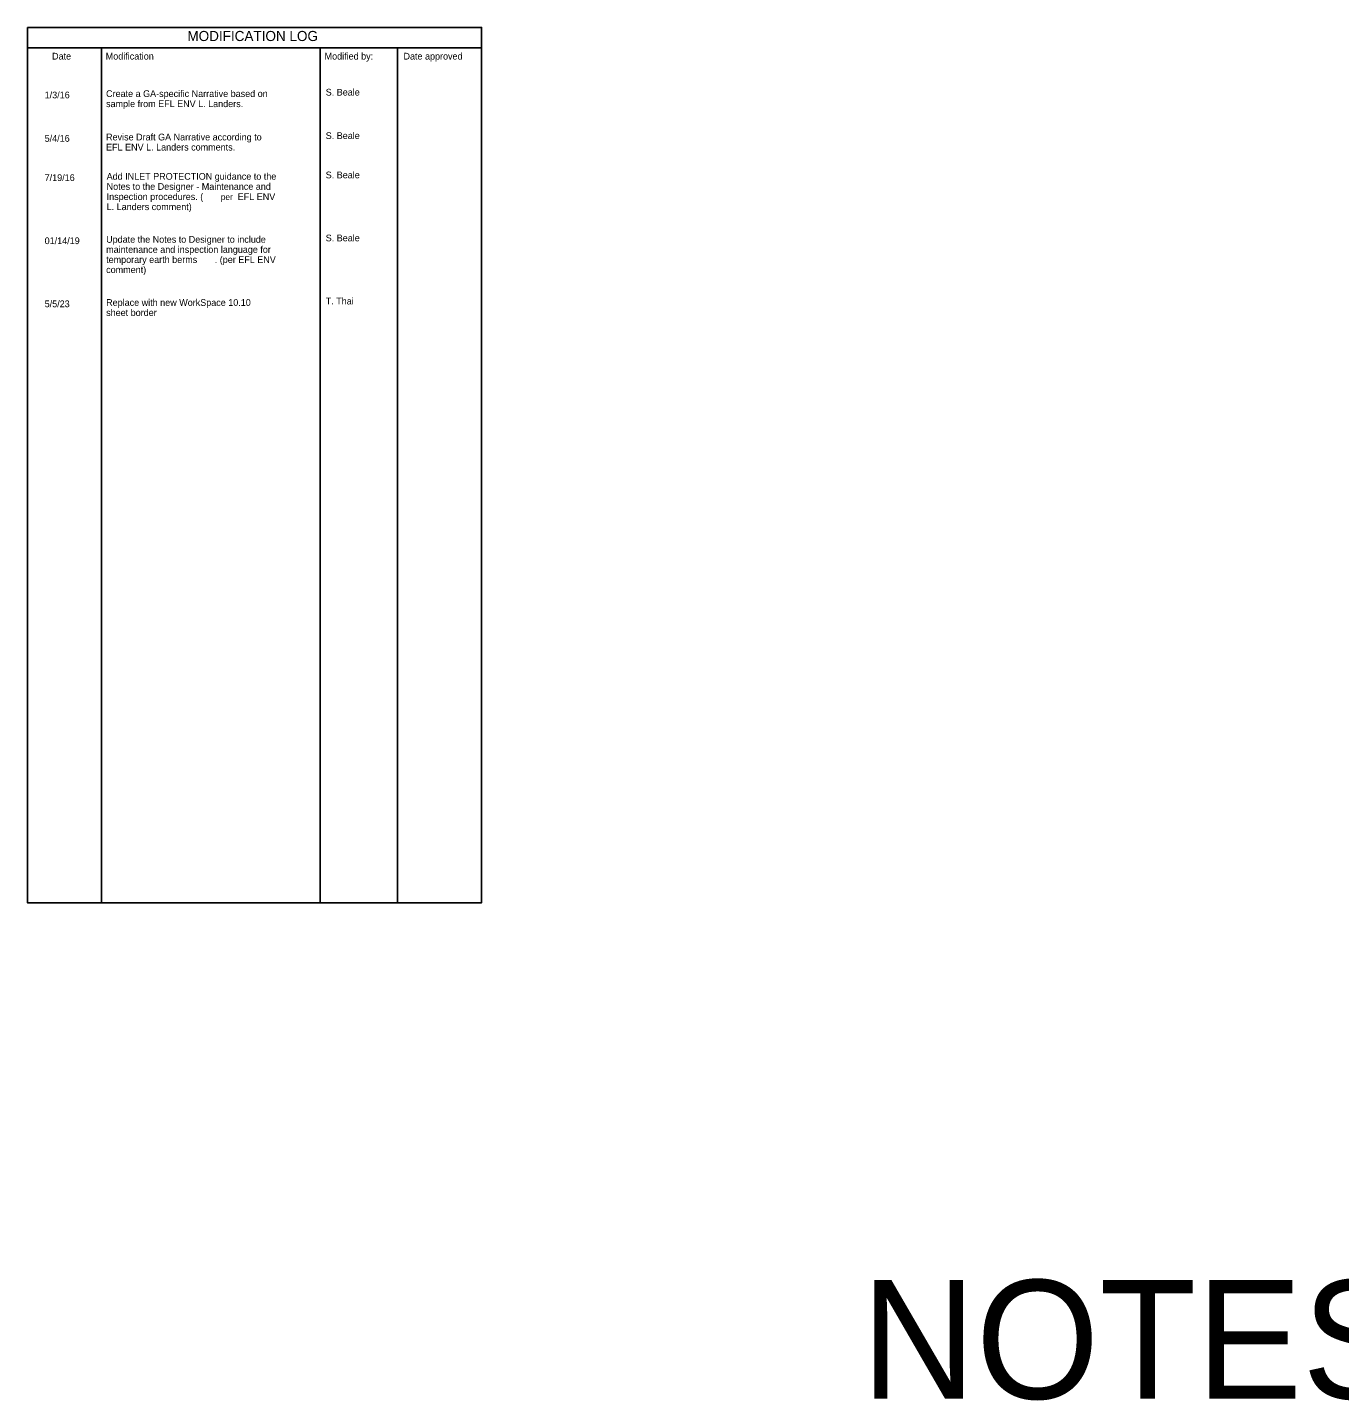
# Model space of a CAD drawing. Extents: x -126 to 11774, y -1769 to 1078.
# Drawn here: x -19 to 1540, y -1769 to -137 of the extents above; entities that cross this region are included whole.
import ezdxf

# ---------------------------------------------------------------- set-up
doc = ezdxf.new("R2010")
doc.units = 0
doc.layers.add('D_Tables', color=7, linetype='Continuous')
doc.layers.add('Default', color=7, linetype='Continuous')

msp = doc.modelspace()

# ---------------------------------------------------------------- linework, layer by layer
at = {"layer": 'D_Tables'}
for p, q in [((-19.4, -161.2), (520.6, -161.2)), ((68.6, -161.2), (68.6, -1177.2)), ((328.6, -161.2), (328.6, -1177.2)), ((420.6, -161.2), (420.6, -1177.2))]:
    msp.add_line(p, q, dxfattribs=at)
msp.add_lwpolyline([(-19.4, -137.2), (520.6, -137.2), (520.6, -1177.2), (-19.4, -1177.2)], close=True, dxfattribs=at)

# ---------------------------------------------------------------- texts
for s, height, p in [('MODIFICATION LOG', 12.008, (170.8, -153.3)), ('Date', 8.01, (9.9, -175.3)), ('Modification', 8.005, (73.7, -175.3)), ('Modified by:', 8.005, (333.9, -175.3)), ('Date approved', 8.005, (427.7, -175.3)), ('S. Beale', 8.01, (335.2, -218.1)), ('S. Beale', 8.01, (335.2, -269.7)), ('Add INLET PROTECTION guidance to the', 8.005, (74.8, -318.1)), ('S. Beale', 8.01, (335.2, -316.4)), ('Notes to the Designer - Maintenance and', 8.005, (74.8, -330.1)), ('Inspection procedures. (', 8.005, (74.8, -342.2)), ('per ', 7.34, (210.5, -342.2)), ('EFL ENV ', 8.01, (230.6, -342.2)), ('L. Landers comment)', 8.005, (74.8, -354.2))]:
    msp.add_text(s, height=height, rotation=360, dxfattribs=at).set_placement(p)
for s, height, p in [('Create a GA-specific Narrative based on', 8.005, (74.1, -219.8)), ('1/3/16', 8.01, (1.1, -221.4)), ('sample from EFL ENV L. Landers.', 8.005, (74.1, -231.8)), ('5/4/16', 8.01, (1.1, -273)), ('Revise Draft GA Narrative according to', 8.005, (74.1, -271.4)), ('EFL ENV L. Landers comments.', 8.005, (74.1, -283.4)), ('7/19/16', 8.01, (1.1, -319.6)), ('01/14/19', 8.01, (1.1, -394.6)), ('Update the Notes to Designer to include', 8.005, (74.2, -393)), ('S. Beale', 8.01, (335.2, -391.3)), ('maintenance and inspection language for', 8.005, (74.2, -405)), ('temporary earth berms', 8.005, (74.2, -417)), ('comment)', 8.01, (74.2, -429)), ('. (per EFL ENV', 8.005, (203.3, -417)), ('5/5/23', 8.01, (1.1, -469.6)), ('sheet border', 8.005, (74.2, -480)), ('Replace with new WorkSpace 10.10', 8.005, (74.2, -468)), ('T. Thai', 8.01, (335.2, -466.3))]:
    msp.add_text(s, height=height, dxfattribs=at).set_placement(p)
at = {"layer": 'Default'}
msp.add_text('NOTES TO THE DESIGNER', height=141.138, rotation=360, dxfattribs=at).set_placement((971.8, -1766.7))

doc.saveas('drawing.dxf')
